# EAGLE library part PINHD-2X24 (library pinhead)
PIN HEADER
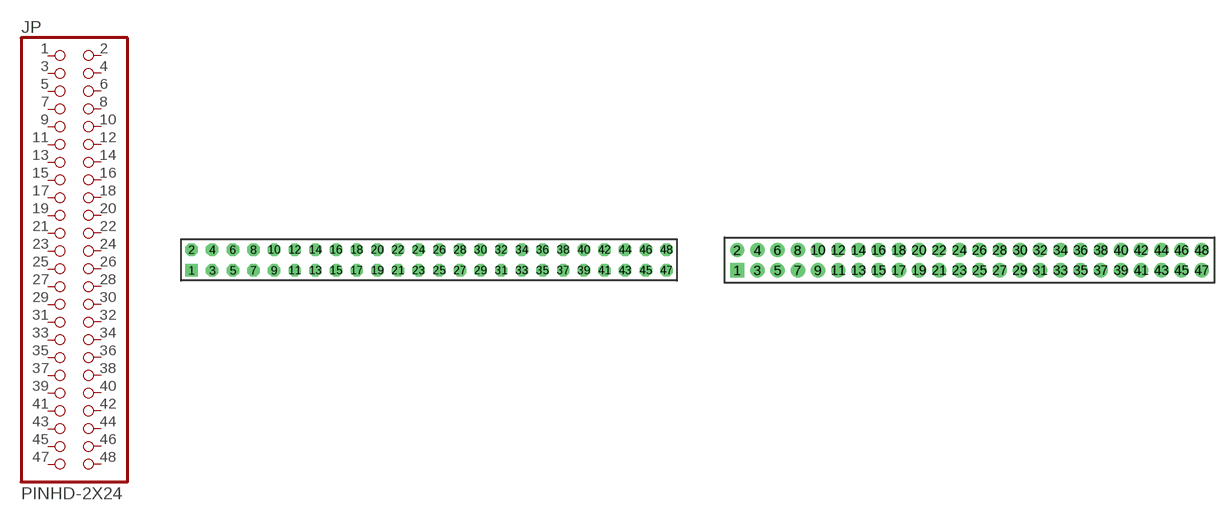
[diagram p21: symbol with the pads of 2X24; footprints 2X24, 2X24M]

Designator prefix JP

## PINHD-2X24  [2X24]
1  1  pas
2  2  pas
3  3  pas
4  4  pas
5  5  pas
6  6  pas
7  7  pas
8  8  pas
9  9  pas
10  10  pas
11  11  pas
12  12  pas
13  13  pas
14  14  pas
15  15  pas
16  16  pas
17  17  pas
18  18  pas
19  19  pas
20  20  pas
21  21  pas
22  22  pas
23  23  pas
24  24  pas
25  25  pas
26  26  pas
27  27  pas
28  28  pas
29  29  pas
30  30  pas
31  31  pas
32  32  pas
33  33  pas
34  34  pas
35  35  pas
36  36  pas
37  37  pas
38  38  pas
39  39  pas
40  40  pas
41  41  pas
42  42  pas
43  43  pas
44  44  pas
45  45  pas
46  46  pas
47  47  pas
48  48  pas

## PINHD-2X24M  [2X24M]
Pads as for 2X24

## Footprint 2X24 (pad centres in mm)
PIN HEADER - 0.1"
drill 1.016 square: 1 -27.94,-1.27
drill 1.016 octagon: 2 -27.94,1.27; 3 -25.4,-1.27; 4 -25.4,1.27; 5 -22.86,-1.27; 6 -22.86,1.27; 7 -20.32,-1.27; 8 -20.32,1.27; 9 -17.78,-1.27; 10 -17.78,1.27; 11 -15.24,-1.27; 12 -15.24,1.27; 13 -12.7,-1.27; 14 -12.7,1.27; 15 -10.16,-1.27; 16 -10.16,1.27; 17 -7.62,-1.27; 18 -7.62,1.27; 19 -5.08,-1.27; 20 -5.08,1.27; 21 -2.54,-1.27; 22 -2.54,1.27; 23 0,-1.27; 24 0,1.27; 25 2.54,-1.27; 26 2.54,1.27; 27 5.08,-1.27; 28 5.08,1.27; 29 7.62,-1.27; 30 7.62,1.27; 31 10.16,-1.27; 32 10.16,1.27; 33 12.7,-1.27; 34 12.7,1.27; 35 15.24,-1.27; 36 15.24,1.27; 37 17.78,-1.27; 38 17.78,1.27; 39 20.32,-1.27; 40 20.32,1.27; 41 22.86,-1.27; 42 22.86,1.27; 43 25.4,-1.27; 44 25.4,1.27; 45 27.94,-1.27; 46 27.94,1.27; 47 30.48,-1.27; 48 30.48,1.27

## Footprint 2X24M (pad centres in mm)
PIN HEADER - 2MM"
drill 0.914 square: 1 -23,-1
drill 0.914 round: 2 -23,1; 3 -21,-1; 4 -21,1; 5 -19,-1; 6 -19,1; 7 -17,-1; 8 -17,1; 9 -15,-1; 10 -15,1; 11 -13,-1; 12 -13,1; 13 -11,-1; 14 -11,1; 15 -9,-1; 16 -9,1; 17 -7,-1; 18 -7,1; 19 -5,-1; 20 -5,1; 21 -3,-1; 22 -3,1; 23 -1,-1; 24 -1,1; 25 1,-1; 26 1,1; 27 3,-1; 28 3,1; 29 5,-1; 30 5,1; 31 7,-1; 32 7,1; 33 9,-1; 34 9,1; 35 11,-1; 36 11,1; 37 13,-1; 38 13,1; 39 15,-1; 40 15,1; 41 17,-1; 42 17,1; 43 19,-1; 44 19,1; 45 21,-1; 46 21,1; 47 23,-1; 48 23,1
